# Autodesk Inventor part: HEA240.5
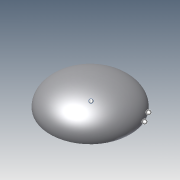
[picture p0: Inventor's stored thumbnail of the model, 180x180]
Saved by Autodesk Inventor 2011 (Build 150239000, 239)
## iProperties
Created: 2010-05
Part Number: HEA240.5
Document SubType Name: Modeling
Designer: mklassen
Density: 1 g/cm^3
Description: HEAD ELLIPSOIDAL 24"x 0.5"
THK: 0.500 in
OD: 24.000 in
LIP: 1.000 in
DRFAC: 0.850 ul
KRFAC: 0.154 ul
Author: mklassen
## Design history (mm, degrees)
sketch "skConical"
  geometry: L1 (0, -94.751)-(0, 568.503) reference; L2 (-104.442, 0)-(378.41, 0) reference; L3 (292.1, 0)-(292.1, 25.4); L4 (275.392, 78.859)-(20.88, 446.264); L5 (0, 457.2)-(-35.463, 457.2); L6 (31.319, 453.496)-(285.832, 86.091); L7 (304.8, 25.4)-(304.8, 0); L8 (292.1, 0)-(304.8, 0); L9 (0, 457.2)-(0, 469.9); A1 r 93.878 centre (198.222, 25.4) between (292.1, 25.4) and (275.392, 78.859); A2 r 25.4 centre (0, 431.8) between (20.88, 446.264) and (0, 457.2); A3 r 38.1 centre (0, 431.8) between (31.319, 453.496) and (0, 469.9); A4 r 106.578 centre (198.222, 25.4) between (304.8, 25.4) and (285.832, 86.091); 1 further point
  constraints: 14 end point, 8 point on circle, 4 centre point, 4 tangent, 2 perpendicular, 2 point on line, 1 collinear, 1 horizontal, 3 other
  dimensions: "d6" = 93.8784 radius of A1 (derived); "d7" = 12.7 distance between parallel lines of L7 L3 (derived); "d8" = 25.4 distance of L3.start L3.end (= LIP); "d9" = 609.6 diameter of L7 L1 (derived); "d10" = 457.2 distance between parallel lines of L5 L2 (derived); "d11" = 25.4 radius of A2
revolve "Conical" sketch "skConical" stored, may be unused: angle "d12" = 90 deg
sketch "skDiffuser"
  geometry: L1 (0, -280.075)-(0, 484.332) reference; L2 (-63.58, 0)-(381.479, 0) reference; L3 (292.1, 0)-(292.1, 142.234); L4 (292.1, 0)-(304.8, 0); L5 (0, -143.029)-(0, -155.729); A1 r 93.878 centre (198.222, 0) between (242.081, -83.003) and (292.1, 0); A2 r 518.16 centre (0, 375.131) between (0, -143.029) and (242.081, -83.003); A3 r 530.86 centre (0, 375.131) between (0, -155.729) and (248.014, -94.232); A4 r 106.578 centre (198.222, 0) between (248.014, -94.232) and (304.8, 0); 1 further point
  constraints: 8 point on circle, 6 end point, 4 centre point, 3 point on line, 2 perpendicular, 2 tangent, 1 collinear, 1 other
  dimensions: "d15" = 93.8784 radius of A1 (derived); "d16" = 518.16 radius of A2 (derived); "d17" = 12.7 distance of L3.start L4.end (derived); "d18" = 609.6 diameter of L4.end L1 (derived)
revolve "Diffuser" sketch "skDiffuser" stored, may be unused: angle "d19" = 90 deg
sketch "skEllipsoidal"
  geometry: L1 (-73.371, 0)-(397.287, 0) reference; L2 (0, -42.808)-(0, 243.852) reference; L3 (292.1, 0)-(304.8, 0); L4 (0, 139.7)-(0, 152.4); 2 further points; 1 other entity
  constraints: 4 end point, 2 point on line, 1 coincident, 1 collinear, 1 horizontal, 1 perpendicular, 7 other
  dimensions: "d22" = 609.6 diameter of L3.end L2 (derived); "d23" = 152.4 distance from line of L4.end L1 (derived); "d24" = 12.7 distance of L3.start L3.end (derived)
revolve "Ellipsoidal" sketch "skEllipsoidal" stored, may be unused: angle "d25" = 90 deg
sketch "skFlat"
  geometry: L1 (-65.375, 0)-(392.248, 0) reference; L2 (0, -30.81)-(0, 184.862) reference; L3 (304.8, 0)-(304.8, 25.4); L4 (198.222, 131.978)-(0, 131.978); L5 (0, 119.278)-(198.222, 119.278); L6 (292.1, 25.4)-(292.1, 0); L7 (0, 119.278)-(0, 131.978); L8 (292.1, 0)-(304.8, 0); A1 r 106.578 centre (198.222, 25.4) between (304.8, 25.4) and (198.222, 131.978); A2 r 93.878 centre (198.222, 25.4) between (292.1, 25.4) and (198.222, 119.278); 1 further point
  constraints: 12 end point, 4 point on circle, 2 centre point, 2 perpendicular, 2 point on line, 2 tangent, 1 collinear, 1 parallel, 2 other
  dimensions: "d28" = 609.6 diameter of L3 L2 (derived); "d31" = 93.8784 radius of A2 (derived); "d32" = 12.7 distance of L6.end L3.start (derived); "d33" = 25.4 distance of L6.start L6.end (= LIP)
revolve "Flat" sketch "skFlat" stored, may be unused: angle "d34" = 90 deg
sketch "skHemispherical"
  geometry: L1 (0, -73.585)-(0, 441.511) reference; L2 (-73.585, 0)-(441.511, 0) reference; L3 (292.1, 0)-(304.8, 0); L4 (0, 292.1)-(0, 304.8); A1 r 304.8 centre (0, 0) between (304.8, 0) and (0, 304.8); A2 r 292.1 centre (0, 0) between (292.1, 0) and (0, 292.1); 1 further point
  constraints: 5 point on circle, 4 end point, 2 centre point, 2 collinear, 2 point on line, 1 coincident
  dimensions: "d37" = 609.6 diameter of L3.end L1 (derived); "d38" = 12.7 distance of L3.start L3.end (derived)
revolve "Hemispherical" sketch "skHemispherical" stored, may be unused: angle "d39" = 90 deg
sketch "skTorispherical"
  geometry: L1 (-63.58, 0)-(381.479, 0) reference; L2 (0, -458.932)-(0, 305.475) reference; L3 (292.1, 0)-(292.1, 25.4); L4 (304.8, 25.4)-(304.8, 0); L5 (292.1, 0)-(304.8, 0); L6 (0, 168.429)-(0, 181.129); A1 r 93.878 centre (198.222, 25.4) between (292.1, 25.4) and (242.081, 108.403); A2 r 518.16 centre (0, -349.731) between (242.081, 108.403) and (0, 168.429); A3 r 530.86 centre (0, -349.731) between (248.014, 119.632) and (0, 181.129); A4 r 106.578 centre (198.222, 25.4) between (304.8, 25.4) and (248.014, 119.632); 1 further point
  constraints: 8 end point, 8 point on circle, 4 centre point, 2 perpendicular, 2 point on line, 2 tangent, 1 collinear, 1 vertical alignment, 2 other
  dimensions: "d43" = 25.4 distance of L3.start L3.end (= LIP); "d44" = 93.8784 radius of A1 (derived); "d45" = 518.16 radius of A2 (derived); "d46" = 12.7 distance of L3.start L4.end (derived); "d47" = 609.6 diameter of L4 L2 (derived)
revolve "Torispherical" sketch "skTorispherical" stored, may be unused: angle "d48" = 90 deg
body "Solid1"
other parameters: "LIP" = 25.4 [user parameter; used in 3 equation terms], "DRFAC" = 0.85 [user parameter; used in 2 equation terms], "KRFAC" = 0.154 [user parameter; used in 4 equation terms], "d13" = 0, "d14" = 0, "d20" = 0, "d21" = 0, "d26" = 0, "d27" = 0, "d35" = 0, "d36" = 0, "d40" = 0, "d41" = 0, "d49" = 0, "d50" = 0, "d51" = 0, "d52" = 0
